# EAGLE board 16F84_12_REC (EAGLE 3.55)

Size 160 x 100 mm. Coordinates in mm from the lower left corner, seen from the top.
Outline: 0,0 160,0 160,100 0,100 0,0
Copper layers used: 

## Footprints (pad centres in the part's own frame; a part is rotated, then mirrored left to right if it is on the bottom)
RM2,5 = drill 0.813 pad 1.422 round:  0,0;  2.54,0
KO01 = drill 0.813 pad 1.422 round:  0,0;  2.54,0
O_1A = drill 1.016 pad 2.032 round:  0,0;  10.16,0
L-18B = drill 0.61 pad 3.048 offset:  0,0;  2.54,0;  15.24,0;  17.78,0;  5.08,0;  7.62,0;  12.7,0;  10.16,0;  20.32,0;  20.32,7.62;  17.78,7.62;  15.24,7.62;  12.7,7.62;  10.16,7.62;  7.62,7.62;  5.08,7.62;  2.54,7.62;  0,7.62
OP1836 = drill 0.813 pad 1.778 round:  0,0;  2.54,0;  5.08,0
REC = drill 0.813 pad 1.778 round:  0,0;  2.54,0;  7.62,0
D_5MM = drill 0.813 pad 1.422 round:  -1.27,0;  1.27,0
GEL = drill 1.295 pad 3.048 round:  0,0
ARZ_ST = drill 0.813 pad 1.422 round:  0,0;  5.08,0
S04 = drill 0.406 pad 1.778 round:  0,0;  10.16,0
HRUNG = drill 3.505 pad 6.452 round:  0,0
220A = drill 1.016 pad 3.048 offset:  -2.54,0;  0,0;  2.54,0

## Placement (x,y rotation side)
C1  27p  [RM2,5]  not placed on the board
C2  100n  [RM2,5]  not placed on the board
C3  27p  [RM2,5]  not placed on the board
C4  100n  [RM2,5]  not placed on the board
C5  100u  [KO01]  not placed on the board
C6  47u  [KO01]  not placed on the board
D1  1N4001  [O_1A]  not placed on the board
IC1  16F84P  [L-18B]  not placed on the board
IC2  TSOP1836  [OP1836]  not placed on the board
IC3  TSOP1736  [REC]  not placed on the board
LED1  CM8  [D_5MM]  not placed on the board
LED2  CM9  [D_5MM]  not placed on the board
LED3  CM10  [D_5MM]  not placed on the board
LED4  CM11  [D_5MM]  not placed on the board
LED5  CM0  [D_5MM]  not placed on the board
LED6  CM1  [D_5MM]  not placed on the board
LED7  CM2  [D_5MM]  not placed on the board
LED8  CM3  [D_5MM]  not placed on the board
LED9  CM4  [D_5MM]  not placed on the board
LED10  CM5  [D_5MM]  not placed on the board
LED11  CM6  [D_5MM]  not placed on the board
LED12  CM7  [D_5MM]  not placed on the board
N1  +  [GEL]  not placed on the board
N2  -  [GEL]  not placed on the board
Q1  4MHz  [ARZ_ST]  not placed on the board
R1  270  [S04]  not placed on the board
R2  270  [S04]  not placed on the board
R3  270  [S04]  not placed on the board
R4  10k  [S04]  not placed on the board
R5  270  [S04]  not placed on the board
R6  270  [S04]  not placed on the board
R7  270  [S04]  not placed on the board
R8  270  [S04]  not placed on the board
R9  270  [S04]  not placed on the board
R10  270  [S04]  not placed on the board
R11  270  [S04]  not placed on the board
R12  270  [S04]  not placed on the board
R13  270  [S04]  not placed on the board
U$15  BOHRUNG  [HRUNG]  not placed on the board
U$16  BOHRUNG  [HRUNG]  not placed on the board
U$26  BOHRUNG  [HRUNG]  not placed on the board
U$27  BOHRUNG  [HRUNG]  not placed on the board
VR1  7805  [220A]  not placed on the board

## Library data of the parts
C1-C6 D1 LED1-LED12 N1 N2 R3-R8 U$15 U$16 U$26 U$27 = holgnorm
IC1 = PIC
IC2 IC3 = ic_holg
Q1 = bts
R1 R2 R9-R13 VR1 = holg_plt

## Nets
+5V: C2. C6. IC1. IC2. IC3. R4. VR1.
+UB: C5. D1. VR1.
GND: C1. C2. C3. C4. C5. C6. IC1. IC2. IC3. LED1. LED2. LED3. LED4. LED5. LED6. LED7. LED8. LED9. LED10. LED11. LED12. N2. U$15. U$16. U$26. U$27. VR1.
N$1: C1. IC1. Q1.
N$2: D1. N1.
N$3: C3. IC1. Q1.
N$4: LED12. R13.
N$5: C4. IC1. R4.
N$6: IC1. R3.
N$7: LED11. R12.
N$8: IC1. R1.
N$9: IC1. IC2. IC3.
N$10: LED10. R11.
N$11: IC1. R2.
N$12: IC1. R5.
N$13: IC1. R6.
N$14: IC1. R7.
N$15: IC1. R8.
N$16: LED4. R8.
N$17: LED3. R7.
N$18: LED2. R6.
N$19: LED1. R5.
N$20: LED9. R10.
N$21: IC1. R9.
N$22: LED8. R9.
N$23: LED7. R2.
N$24: LED6. R3.
N$25: LED5. R1.
N$26: IC1. R10.
N$27: IC1. R11.
N$28: IC1. R12.
N$29: IC1. R13.

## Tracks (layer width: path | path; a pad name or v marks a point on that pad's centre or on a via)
+5V  (6 unrouted)
+UB  (2 unrouted)
GND  (26 unrouted)
N$1  (2 unrouted)
N$2  (1 unrouted)
N$3  (2 unrouted)
N$4  (1 unrouted)
N$5  (2 unrouted)
N$6  (1 unrouted)
N$7  (1 unrouted)
N$8  (1 unrouted)
N$9  (2 unrouted)
N$10  (1 unrouted)
N$11  (1 unrouted)
N$12  (1 unrouted)
N$13  (1 unrouted)
N$14  (1 unrouted)
N$15  (1 unrouted)
N$16  (1 unrouted)
N$17  (1 unrouted)
N$18  (1 unrouted)
N$19  (1 unrouted)
N$20  (1 unrouted)
N$21  (1 unrouted)
N$22  (1 unrouted)
N$23  (1 unrouted)
N$24  (1 unrouted)
N$25  (1 unrouted)
N$26  (1 unrouted)
N$27  (1 unrouted)
N$28  (1 unrouted)
N$29  (1 unrouted)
